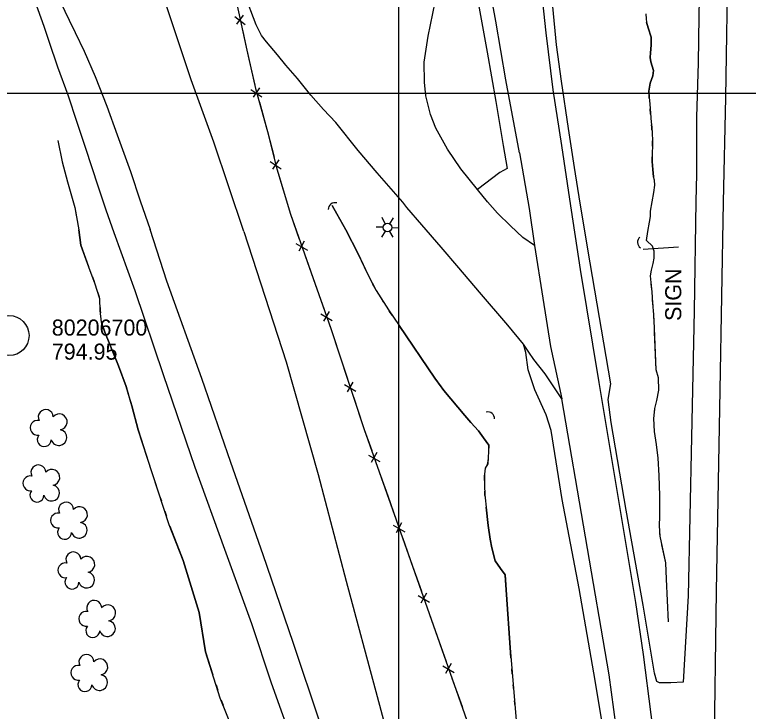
# Model space of a CAD drawing. Extents: x 591954 to 597000, y 198576 to 213500.
# Drawn here: x 593856.4 to 594130.7, y 210268.9 to 210529.3 of the extents above; entities that cross this region are included whole.
import ezdxf

# ---------------------------------------------------------------- set-up
doc = ezdxf.new("R2010")
doc.units = 0
for name, color, linetype in [('Level 10', 7, 'Continuous'), ('Level 11', 7, 'Continuous'), ('Level 14', 7, 'Continuous'), ('Level 15', 7, 'Continuous'), ('Level 17', 7, 'Continuous'), ('Level 18', 7, 'Continuous'), ('Level 19', 7, 'Continuous'), ('Level 6', 7, 'Continuous')]:
    doc.layers.add(name, color=color, linetype=linetype)

msp = doc.modelspace()

# ---------------------------------------------------------------- linework, layer by layer
at = {"layer": 'Level 10'}
for p, q in [((594000, 210000), (594000, 211500)), ((593000, 210500), (595000, 210500)), ((593000, 210500), (595000, 210500)), ((594000, 209500), (594000, 210500))]:
    msp.add_line(p, q, dxfattribs=at)
at = {"layer": 'Level 11'}
for points in [[(594121.44, 210459.17), (594122.25, 210498.37), (594123.17, 210553.35), (594124.43, 210619.5), (594125, 210654.8), (594125.89, 210695.68), (594126.54, 210724.61), (594127.4, 210770.31), (594128.28, 210818.66), (594129.2, 210852.3), (594130.02, 210894.89), (594130.64, 210948.86), (594131.88, 210991.76), (594132.98, 211045.17), (594133.71, 211089.02), (594134.68, 211134.48), (594135.32, 211176), (594136.16, 211221.31), (594137.06, 211262.73), (594137.74, 211300.23), (594138.56, 211351.93)], [(593942.07, 210448.25), (593930.85, 210481.68), (593922.36, 210504.92), (593910.35, 210541.32), (593899.7, 210573.1), (593890.09, 210602.43), (593883.59, 210625.68), (593877.84, 210646.9), (593873.2, 210666.64), (593869.3, 210687.68), (593866.01, 210709.44), (593862.8, 210734.46), (593861.17, 210753.61), (593859.27, 210774.78), (593858.05, 210801.65), (593857.58, 210822.9), (593857.85, 210841.64), (593858.43, 210868.75), (593859.89, 210897.29), (593861.7, 210920.91), (593863.15, 210937.74)], [(594119.5, 210897.15), (594119.11, 210872.03), (594118.75, 210854.96), (594118.55, 210842.77), (594117.96, 210823.25), (594117.65, 210803.96), (594117.31, 210788.66), (594116.78, 210767.34), (594116.67, 210749.31), (594116.07, 210721.82), (594115.43, 210697.32), (594115.23, 210679.05), (594114.7, 210660.36), (594114.36, 210644.35), (594114.05, 210623.86), (594113.82, 210608.1), (594113.47, 210586.67), (594113.12, 210567.42), (594112.64, 210548.64), (594112.24, 210528.59), (594111.95, 210511.33), (594111.37, 210491), (594111.28, 210469.69), (594111.11, 210459.41)], [(594067.79, 210458.8), (594065.74, 210472.13), (594063.48, 210486.77), (594060.86, 210504.43), (594059.05, 210518.08), (594057.57, 210532.37), (594056.44, 210546), (594055.34, 210563.63), (594054.72, 210575.21), (594053.91, 210589.34), (594053.37, 210602.59), (594052.94, 210616.5), (594052.36, 210628.63), (594050.81, 210636.84), (594050.76, 210636.93), (594049.71, 210639.08)], [(594049.58, 210636.24), (594048.85, 210620.42), (594049.91, 210596.12), (594050.93, 210572.6), (594051.93, 210557.21), (594053.06, 210541.25), (594055.07, 210522.51), (594057.64, 210501.23), (594060.85, 210480.44), (594063.89, 210460.29)], [(593843.08, 210598.67), (593845.38, 210594.07), (593849.99, 210583.91), (593854.27, 210574.15), (593857.61, 210566.92), (593863.38, 210555.19), (593868.73, 210544.33), (593872.11, 210537.16), (593876.83, 210527.22), (593879.02, 210522.67), (593882.39, 210515.71), (593886.58, 210506.13), (593890.87, 210495.04), (593894.74, 210484.33), (593899.7, 210470.71), (593903.39, 210459.76), (593907.11, 210448.98)], [(593841.29, 210597.07), (593844.94, 210590.76), (593847.94, 210583.97), (593849.65, 210580.12), (593850.99, 210576.15), (593852.68, 210571.42), (593853.7, 210565.18), (593859.93, 210545.62), (593867.28, 210524.99), (593869.24, 210519.44), (593872.42, 210509.79), (593876.27, 210499.29), (593879.61, 210489.15), (593882.75, 210479.82), (593887.66, 210464.91), (593890.45, 210456.32), (593893.5, 210447.84)], [(594045.12, 210477.67), (594040.09, 210504.98), (594036.26, 210526.83), (594029.95, 210561.61), (594026.41, 210581.46)], [(594023.07, 210569.57), (594024.32, 210563.79), (594026.72, 210549.95), (594029.84, 210533.05), (594033.03, 210515.28), (594036.35, 210496.78), (594039.01, 210480.39), (594040.51, 210471.73), (594037.83, 210470.27), (594029.45, 210463.89)], [(594045.12, 210477.67), (594048.8, 210456.85), (594050.73, 210443.03)], [(594063.89, 210460.29), (594067.88, 210434.02)], [(594111.11, 210459.41), (594110.44, 210418.55), (594109.47, 210371.37), (594108.25, 210312.09), (594106.37, 210279.75), (594101.72, 210279.48), (594097.52, 210279.46), (594096.52, 210279.97), (594095.67, 210283.11), (594091.39, 210308.61), (594085.09, 210344.1), (594079.44, 210376.81), (594078.32, 210385.39), (594079.29, 210391.23), (594071.63, 210436.49), (594067.79, 210458.8)], [(594112.45, 210007.48), (594112.6, 209995.63), (594113.36, 210005.05), (594114.01, 210051.04), (594114.57, 210090.36), (594115.82, 210144.23), (594116.82, 210196.5), (594117.98, 210250.27), (594118.86, 210313.77), (594120.19, 210388.92), (594121.44, 210459.17)], [(593893.5, 210447.84), (593901.37, 210426.15), (593911.91, 210394.74), (593923.81, 210360.09), (593934.82, 210329.5), (593944.91, 210301.67), (593952.33, 210279.54), (593961.41, 210254.08), (593968.08, 210234.1), (593973.48, 210217.01), (593976.27, 210205.8), (593979.78, 210188.24), (593982.77, 210173.87), (593990.03, 210133.11), (593995.73, 210101.29), (593997.53, 210082.52)], [(594012.23, 209875.28), (594012.83, 209907.2), (594013.56, 209961.14), (594013.42, 210007.19), (594011.79, 210044.49), (594010.21, 210070.27), (594008.55, 210088.06), (594005.46, 210114.13), (594001.26, 210142.91), (593996.29, 210169.22), (593988.63, 210201.88), (593979.1, 210236.56), (593970.66, 210264.38), (593960.5, 210294.59), (593949.39, 210327.37), (593937.21, 210361.92), (593926.35, 210393.26), (593913.33, 210429.68), (593907.11, 210448.98)], [(593942.07, 210448.25), (593957.88, 210399.56), (593969.83, 210357.39), (593980.31, 210317.58), (593991.98, 210274.43), (594000.82, 210241.35), (594009.56, 210209.35), (594011.94, 210199.89), (594018.95, 210168.92), (594024.25, 210136.89), (594028.47, 210108.67), (594033.02, 210055.42), (594034.11, 210025.42), (594035.11, 209986.5), (594035.04, 209949.68), (594034.73, 209920.64), (594034.04, 209883.08), (594033, 209841.22)], [(594050.73, 210443.03), (594053.94, 210423.27), (594056.79, 210405.29), (594060.94, 210385.67)], [(594067.88, 210434.02), (594074.79, 210391.75)], [(594092.35, 209863.88), (594091.82, 209896.8), (594091.24, 209929.86), (594091.25, 209960.38), (594090.88, 209992.79), (594091.06, 210019.73), (594090.91, 210056.44), (594090.22, 210091.74), (594089.01, 210134.66), (594087.71, 210160.54), (594086.15, 210184.87), (594083.33, 210209.14), (594080.3, 210234.14), (594076.96, 210259.51), (594072.96, 210283.2), (594067.46, 210314.76), (594061.12, 210348.1), (594056.98, 210373.8), (594055.1, 210379.68), (594050.91, 210389.09), (594048.36, 210396.52), (594047.53, 210402.97), (594046.65, 210406.15)], [(594074.79, 210391.75), (594088.54, 210309.54), (594091.45, 210290.13), (594097.18, 210245.19), (594102.08, 210196.34), (594106.03, 210146.88), (594108.81, 210103.15), (594110.99, 210053.56), (594112.45, 210007.48)], [(594091.31, 209554.07), (594092.34, 209600.93), (594093.45, 209653.95), (594094.63, 209705.34), (594096.03, 209775.4), (594097.26, 209853.63), (594097.48, 209924.76), (594097.61, 209991.03), (594097.47, 210057.15), (594095.7, 210107.83), (594092.7, 210159.9), (594089.31, 210197.02), (594083.96, 210243.66), (594078.7, 210282.56), (594060.94, 210385.67)]]:
    msp.add_lwpolyline(points, dxfattribs=at)
at = {"layer": 'Level 14'}
for p, q in [((593994.99, 210451.16), (593993.79, 210453.46)), ((593996.69, 210451.15), (593998.06, 210453.38)), ((593994.16, 210449.8), (593991.55, 210449.87)), ((593994.91, 210448.31), (593993.55, 210446.12)), ((593996.55, 210448.26), (593997.79, 210446.08)), ((593997.43, 210449.71), (593999.95, 210449.64))]:
    msp.add_line(p, q, dxfattribs=at)
msp.add_lwpolyline([(594104.57, 210442.41), (594091.41, 210441.49)], dxfattribs=at)
msp.add_circle((593995.79, 210449.73), 1.64, dxfattribs=at)
at = {"layer": 'Level 15'}
for p, q in [((593938.69, 210528.59), (593942.64, 210525.65)), ((593941.89, 210529.11), (593939.38, 210525.71)), ((593944.76, 210501.3), (593948.89, 210498.59)), ((593947.93, 210502.01), (593945.63, 210498.46)), ((593955.19, 210475.07), (593952.8, 210471.58)), ((593952, 210474.43), (593956.06, 210471.64)), ((593961.58, 210443.72), (593965.87, 210441.29)), ((593964.69, 210444.64), (593962.63, 210440.95)), ((593970.86, 210417.45), (593975.15, 210415.02)), ((593973.97, 210418.37), (593971.91, 210414.68)), ((593979.71, 210391.07), (593983.96, 210388.56)), ((593982.84, 210391.93), (593980.71, 210388.28)), ((593991.78, 210365.58), (593989.72, 210361.88)), ((593988.67, 210364.65), (593992.96, 210362.23)), ((593997.98, 210338.4), (594002.27, 210335.97)), ((594001.09, 210339.32), (593999.03, 210335.63)), ((594010.34, 210313.03), (594008.27, 210309.35)), ((594007.23, 210312.12), (594011.52, 210309.69)), ((594016.47, 210285.84), (594020.76, 210283.41)), ((594019.58, 210286.75), (594017.52, 210283.06))]:
    msp.add_line(p, q, dxfattribs=at)
for points in [[(593891.01, 210717.34), (593892.91, 210703.57), (593895.2, 210687.21), (593898.66, 210671.57), (593902.74, 210657.29), (593907.53, 210643.16), (593913.17, 210628.68), (593918.73, 210615.39), (593924.73, 210601.09), (593930.54, 210587.7), (593936.34, 210573.84), (593939.71, 210566.49), (593939.93, 210564.57), (593933.93, 210558.67), (593935.72, 210548.55), (593939.47, 210533.19), (593942.95, 210517.16), (593946.47, 210501.65), (593950.74, 210486.51), (593954.5, 210471.68), (593959.51, 210454.78)], [(593941.54, 210523.66), (593942.95, 210517.16), (593943.98, 210512.61)], [(593943.98, 210512.61), (593946.19, 210502.9)], [(593947.91, 210496.55), (593950.74, 210486.51), (593950.96, 210485.65)], [(593950.96, 210485.65), (593953.41, 210475.99)], [(593955.1, 210469.64), (593958.33, 210458.78)], [(593958.33, 210458.78), (593959.51, 210454.78)], [(593959.51, 210454.78), (593974.64, 210411.96), (593987.13, 210374.2), (593999.11, 210340.41), (594023.86, 210270.06), (594042.85, 210215.9), (594047.69, 210154.51), (594052.6, 210098.45), (594056.62, 210050.32), (594056.88, 210021.22), (594055.97, 209983.92), (594054.43, 209941.9), (594052.89, 209894.6), (594051.91, 209856.12), (594050.87, 209811.42), (594049.91, 209770.63), (594048.71, 209725.59), (594048.4, 209680.32), (594046.97, 209654.07), (594046.43, 209617.89), (594045.25, 209581.13), (594045.27, 209558.54), (594045.21, 209556.37)], [(593959.51, 210454.78), (593962.83, 210445.39)], [(593965.02, 210439.19), (593968.79, 210428.51)], [(593968.79, 210428.51), (593972.11, 210419.12)], [(593974.3, 210412.92), (593974.64, 210411.96), (593977.88, 210402.18)], [(593977.88, 210402.18), (593981, 210392.72)], [(593983.07, 210386.47), (593986.62, 210375.72)], [(593986.62, 210375.72), (593987.13, 210374.2), (593989.92, 210366.33)], [(593992.12, 210360.13), (593995.91, 210349.46)], [(593995.91, 210349.46), (593999.11, 210340.41), (593999.23, 210340.07)], [(594001.42, 210333.86), (594005.18, 210323.18)], [(594005.18, 210323.18), (594008.48, 210313.79)], [(594010.67, 210307.58), (594014.42, 210296.9)], [(594014.42, 210296.9), (594017.73, 210287.51)], [(594019.91, 210281.3), (594023.67, 210270.62)], [(594023.67, 210270.62), (594023.86, 210270.06), (594026.96, 210261.23)]]:
    msp.add_lwpolyline(points, dxfattribs=at)
for centre, start, end in [((593976.19, 210456.5), 74.8766, 181.1162), ((594091.8, 210444.23), 129.6936, 235.9332), ((594033.32, 210378.29), 357.0272, 103.2667)]:
    msp.add_arc(centre, 2.5, start, end, dxfattribs=at)
at = {"layer": 'Level 17'}
for points in [[(594033.14, 210459.35), (594029.45, 210463.89), (594023.23, 210471.67), (594018.25, 210478.97), (594013.91, 210486.89), (594011.89, 210492.02), (594010.19, 210498.96), (594009.69, 210504.11), (594009.58, 210511.58), (594010.96, 210521.26), (594013.65, 210533.93), (594015.41, 210541.68), (594017.99, 210551.63), (594020.28, 210559.64), (594023.07, 210569.57), (594026.41, 210581.46)], [(594001.55, 210459.21), (593991.98, 210470.11), (593984.81, 210478.54), (593976.44, 210488.94), (593971.92, 210493.85), (593967.2, 210499.15), (593962.11, 210505.47), (593957.81, 210510.38), (593954.67, 210514.3), (593950.57, 210519.15), (593948.67, 210521.52), (593946.72, 210525.49), (593942.32, 210537.08)], [(594060.94, 210385.67), (594054.75, 210395.07), (594050.57, 210400.42), (594048.71, 210403.13), (594046.65, 210406.15), (594040.8, 210413.2), (594030.16, 210425.61), (594022.54, 210434.61), (594015.86, 210442.36), (594008.68, 210450.79), (594003, 210457.27), (594001.55, 210459.21)], [(594050.73, 210443.03), (594046.43, 210446.04), (594041.83, 210450.39), (594036.89, 210455.05), (594033.14, 210459.35)], [(594060.94, 210385.67), (594060.94, 210385.67)]]:
    msp.add_lwpolyline(points, dxfattribs=at)
at = {"layer": 'Level 18'}
for centre, radius, start, end in [((593868.03, 210378.91), 2.78, 1.3946, 209.1675), ((593873.07, 210377.06), 2.97, 278.4237, 139.6575), ((593865.03, 210374.84), 2.78, 78.0716, 279.0826), ((593872.96, 210371.2), 2.97, 196.0745, 79.0477), ((593867.49, 210370.44), 2.61, 140.7797, 358.7123), ((593865.28, 210358.17), 2.78, 1.3946, 209.1675), ((593870.32, 210356.31), 2.97, 278.4237, 139.6575), ((593862.28, 210354.1), 2.78, 78.0716, 279.0826), ((593870.21, 210350.46), 2.97, 196.0745, 79.0477), ((593864.74, 210349.7), 2.61, 140.7797, 358.7123), ((593875.61, 210344.27), 2.78, 1.3946, 209.1675), ((593880.65, 210342.41), 2.97, 278.4237, 139.6575), ((593872.61, 210340.19), 2.78, 78.0716, 279.0826), ((593880.54, 210336.56), 2.97, 196.0745, 79.0477), ((593875.07, 210335.79), 2.61, 140.7797, 358.7123), ((593878.37, 210325.66), 2.78, 1.3946, 209.1675), ((593883.41, 210323.8), 2.97, 278.4237, 139.6575), ((593875.37, 210321.58), 2.78, 78.0716, 279.0826), ((593877.83, 210317.18), 2.61, 140.7797, 358.7123), ((593883.3, 210317.95), 2.97, 196.0745, 79.0477), ((593886.17, 210307.55), 2.78, 1.3946, 209.1675), ((593891.21, 210305.69), 2.97, 278.4237, 139.6575), ((593883.17, 210303.47), 2.78, 78.0716, 279.0826), ((593891.1, 210299.83), 2.97, 196.0745, 79.0477), ((593885.63, 210299.07), 2.61, 140.7797, 358.7123), ((593883.23, 210287.34), 2.78, 1.3946, 209.1675), ((593888.27, 210285.48), 2.97, 278.4237, 139.6575), ((593880.23, 210283.26), 2.78, 78.0716, 279.0826), ((593882.69, 210278.86), 2.61, 140.7797, 358.7123), ((593888.16, 210279.63), 2.97, 196.0745, 79.0477)]:
    msp.add_arc(centre, radius, start, end, dxfattribs=at)
at = {"layer": 'Level 19'}
for points in [[(594092.39, 210529.58), (594092.49, 210527.8), (594092.68, 210526.46)], [(594092.68, 210526.46), (594093.29, 210524.34), (594094.35, 210520.95), (594094.38, 210517.86), (594094.1, 210515.06), (594093.98, 210513.23), (594094.27, 210511.66), (594095.22, 210508.47), (594095, 210506.41), (594093.99, 210503.74), (594093.54, 210500.7), (594093.66, 210498.46), (594093.95, 210495.85), (594094.4, 210489.13), (594094.59, 210487.24), (594094.76, 210485), (594094.9, 210482.31), (594094.93, 210479.9), (594094.72, 210477.92), (594094.73, 210476.38), (594094.81, 210474.36), (594094.97, 210471.36), (594095.22, 210468.72)], [(594093.7, 210498.12), (594093.66, 210498.46), (594093.54, 210500.7), (594093.99, 210503.74), (594095, 210506.41), (594095.22, 210508.47), (594094.27, 210511.66), (594093.98, 210513.23), (594094.1, 210515.06), (594094.38, 210517.86), (594094.35, 210520.95), (594093.29, 210524.34), (594092.68, 210526.46)], [(594094.2, 210492.15), (594094.07, 210494.14)], [(594094.67, 210486.17), (594094.59, 210487.24), (594094.5, 210488.16)], [(593872.54, 210482.32), (593874.2, 210474.33), (593876.17, 210466.85), (593878.9, 210457.22), (593880.39, 210448.82)], [(593872.54, 210482.32), (593874.2, 210474.33), (593876.17, 210466.85), (593878.9, 210457.22), (593879.44, 210454.17)], [(594094.93, 210480.17), (594094.9, 210482.17)], [(594095.22, 210468.72), (594094.97, 210471.36), (594094.81, 210474.36), (594094.74, 210476.18)], [(594092.62, 210444.91), (594093.09, 210448.29), (594093.81, 210451.74), (594094.12, 210453.87), (594094.14, 210455.9), (594095.44, 210462.85), (594095.79, 210465.55), (594095.65, 210467.46), (594095.22, 210468.72)], [(594092.62, 210444.91), (594093.09, 210448.29), (594093.81, 210451.74), (594094.12, 210453.87), (594094.14, 210455.9), (594095.44, 210462.85), (594095.79, 210465.55), (594095.65, 210467.46), (594095.22, 210468.72)], [(593975.09, 210458.01), (593976.88, 210454.83), (593980.2, 210448.89), (593984.83, 210439.83), (593988.58, 210431.92), (593991.56, 210426.24), (593996.16, 210418.94), (594000.2, 210413.16), (594013.57, 210393.43), (594016.86, 210388.83), (594024.74, 210379.5), (594026.91, 210376.85), (594029.82, 210373.71), (594031.7, 210371.11), (594033.75, 210368.33), (594033.36, 210361.36), (594032.38, 210359.74), (594032.06, 210357.57), (594032.05, 210353.38), (594032.26, 210349.78), (594033.39, 210338.34), (594034.19, 210333.16), (594034.83, 210330.01), (594036.07, 210325.12), (594038.02, 210322.31), (594039.75, 210319.9), (594040.18, 210314.22), (594041.8, 210290.88), (594044.71, 210256.57)], [(593988.42, 210432.27), (593984.83, 210439.83), (593980.2, 210448.89), (593976.88, 210454.83), (593975.09, 210458.01)], [(593880.14, 210450.24), (593880.39, 210448.82)], [(593944.57, 210245.8), (593933.29, 210273.81), (593927.81, 210291.09), (593925.45, 210305.82), (593919.37, 210325.28), (593914.22, 210338.59), (593907.77, 210358.08), (593902.58, 210374.09), (593900.2, 210383.05), (593898.1, 210390.26), (593895.21, 210397.98), (593890.07, 210410.58), (593888.91, 210414.31), (593888.41, 210418.76), (593888.27, 210423.1), (593886.37, 210428.98), (593884.61, 210433.58), (593881.18, 210443.14), (593880.39, 210448.82)], [(593880.39, 210448.82), (593881.18, 210443.14), (593884.06, 210435.1)], [(594100.85, 210302.26), (594100.17, 210318.26), (594099.82, 210324.35), (594097.73, 210334.31), (594097.52, 210338.19), (594097.61, 210341.88), (594097.62, 210349.54), (594097.51, 210353.17), (594097.35, 210356.97), (594096.96, 210363.46), (594096.41, 210368.59), (594095.7, 210373.45), (594095.33, 210378.27), (594095.78, 210382.07), (594096.57, 210385.02), (594097.28, 210388.98), (594097.15, 210393.57), (594096.21, 210396.58), (594095.64, 210412.09), (594095.39, 210417.21), (594095.03, 210421.39), (594094.72, 210425.74), (594094.37, 210429.18), (594094.13, 210431.64), (594094.52, 210433.83), (594095.12, 210436.26), (594095.51, 210438.29), (594095.47, 210440.94), (594094.85, 210442.71), (594092.62, 210444.91)], [(594094.28, 210432.47), (594094.52, 210433.83), (594095.12, 210436.26), (594095.51, 210438.29), (594095.47, 210440.94), (594094.85, 210442.71), (594092.62, 210444.91)], [(593885.46, 210431.35), (593886.18, 210429.49)], [(593991.19, 210426.95), (593990.26, 210428.72)], [(594094.64, 210426.51), (594094.44, 210428.5)], [(593887.43, 210425.69), (593888.05, 210423.78)], [(593994.33, 210421.84), (593993.27, 210423.53)], [(594095.1, 210420.53), (594095.03, 210421.39), (594094.95, 210422.52)], [(593888.38, 210419.82), (593888.41, 210418.76), (593888.51, 210417.83)], [(593997.63, 210416.83), (593996.49, 210418.47)], [(594095.52, 210414.55), (594095.43, 210416.54)], [(593889.04, 210413.87), (593890.07, 210410.58), (593895.21, 210397.98), (593898.1, 210390.26), (593899.14, 210386.71)], [(594016.29, 210389.62), (594013.57, 210393.43), (594000.2, 210413.16), (593999.93, 210413.56)], [(594095.75, 210381.87), (594095.78, 210382.07), (594096.57, 210385.02), (594097.28, 210388.98), (594097.15, 210393.57), (594096.21, 210396.58), (594095.7, 210410.55)], [(594033.67, 210366.88), (594033.75, 210368.33), (594031.7, 210371.11), (594029.82, 210373.71), (594026.91, 210376.85), (594024.74, 210379.5), (594016.86, 210388.83), (594016.29, 210389.62)], [(593899.14, 210386.71), (593900.2, 210383.05), (593902.58, 210374.09), (593907.49, 210358.94)], [(594097.51, 210353.01), (594097.51, 210353.17), (594097.35, 210356.97), (594096.96, 210363.46), (594096.41, 210368.59), (594095.7, 210373.45), (594095.33, 210378.27), (594095.75, 210381.87)], [(594033.12, 210360.96), (594033.36, 210361.36), (594033.45, 210362.89)], [(594032.06, 210355.19), (594032.06, 210357.19)], [(593908.74, 210355.15), (593909.37, 210353.25)], [(593910.63, 210349.45), (593911.26, 210347.55)], [(594032.32, 210349.2), (594032.26, 210349.78), (594032.18, 210351.19)], [(594097.62, 210347.01), (594097.62, 210349.01)], [(593912.51, 210343.75), (593913.14, 210341.86)], [(594039.91, 210317.71), (594039.75, 210319.9), (594038.02, 210322.31), (594036.07, 210325.12), (594034.83, 210330.01), (594034.19, 210333.16), (594033.39, 210338.34), (594032.71, 210345.22)], [(594097.59, 210341.01), (594097.61, 210341.88), (594097.61, 210343.01)], [(593914.43, 210338.07), (593919.37, 210325.28), (593923.93, 210310.69)], [(594097.69, 210335.02), (594097.58, 210337.01)], [(594100.85, 210302.26), (594100.17, 210318.26), (594099.82, 210324.35), (594098.41, 210331.09)], [(594041.98, 210288.78), (594041.8, 210290.88), (594040.18, 210314.22), (594039.91, 210317.71)], [(593923.93, 210310.69), (593925.45, 210305.82), (593927.81, 210291.09), (593930.52, 210282.53)], [(594042.48, 210282.8), (594042.32, 210284.79)], [(593931.73, 210278.71), (593932.34, 210276.81)], [(594042.99, 210276.82), (594042.82, 210278.82)], [(593933.61, 210273.02), (593934.36, 210271.16)], [(594043.5, 210270.84), (594043.33, 210272.84)]]:
    msp.add_lwpolyline(points, dxfattribs=at)
at = {"layer": 'Level 6'}
msp.add_circle((593854.3, 210409.33), 7.5, dxfattribs=at)
msp.add_circle((593854.3, 210409.33), 7.5, dxfattribs=at)

# ---------------------------------------------------------------- texts
at = {"layer": 'Level 14'}
msp.add_text('SIGN', height=6, rotation=90, dxfattribs=at).set_placement((594105.65, 210414.8))
at = {"layer": 'Level 6'}
for s, p in [('80206700', (593870.31, 210409.33)), ('80206700', (593870.31, 210409.33)), ('794.95', (593870.31, 210400.33)), ('794.95', (593870.31, 210400.33))]:
    msp.add_text(s, height=6, dxfattribs=at).set_placement(p)

doc.saveas('drawing.dxf')
